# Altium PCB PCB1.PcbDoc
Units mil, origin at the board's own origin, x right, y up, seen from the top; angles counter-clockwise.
Board outline 3900 x 2015 mil, 2 copper layers (Top Layer, Bottom Layer); 36 components, 29 nets, 156 pads, 48 vias.
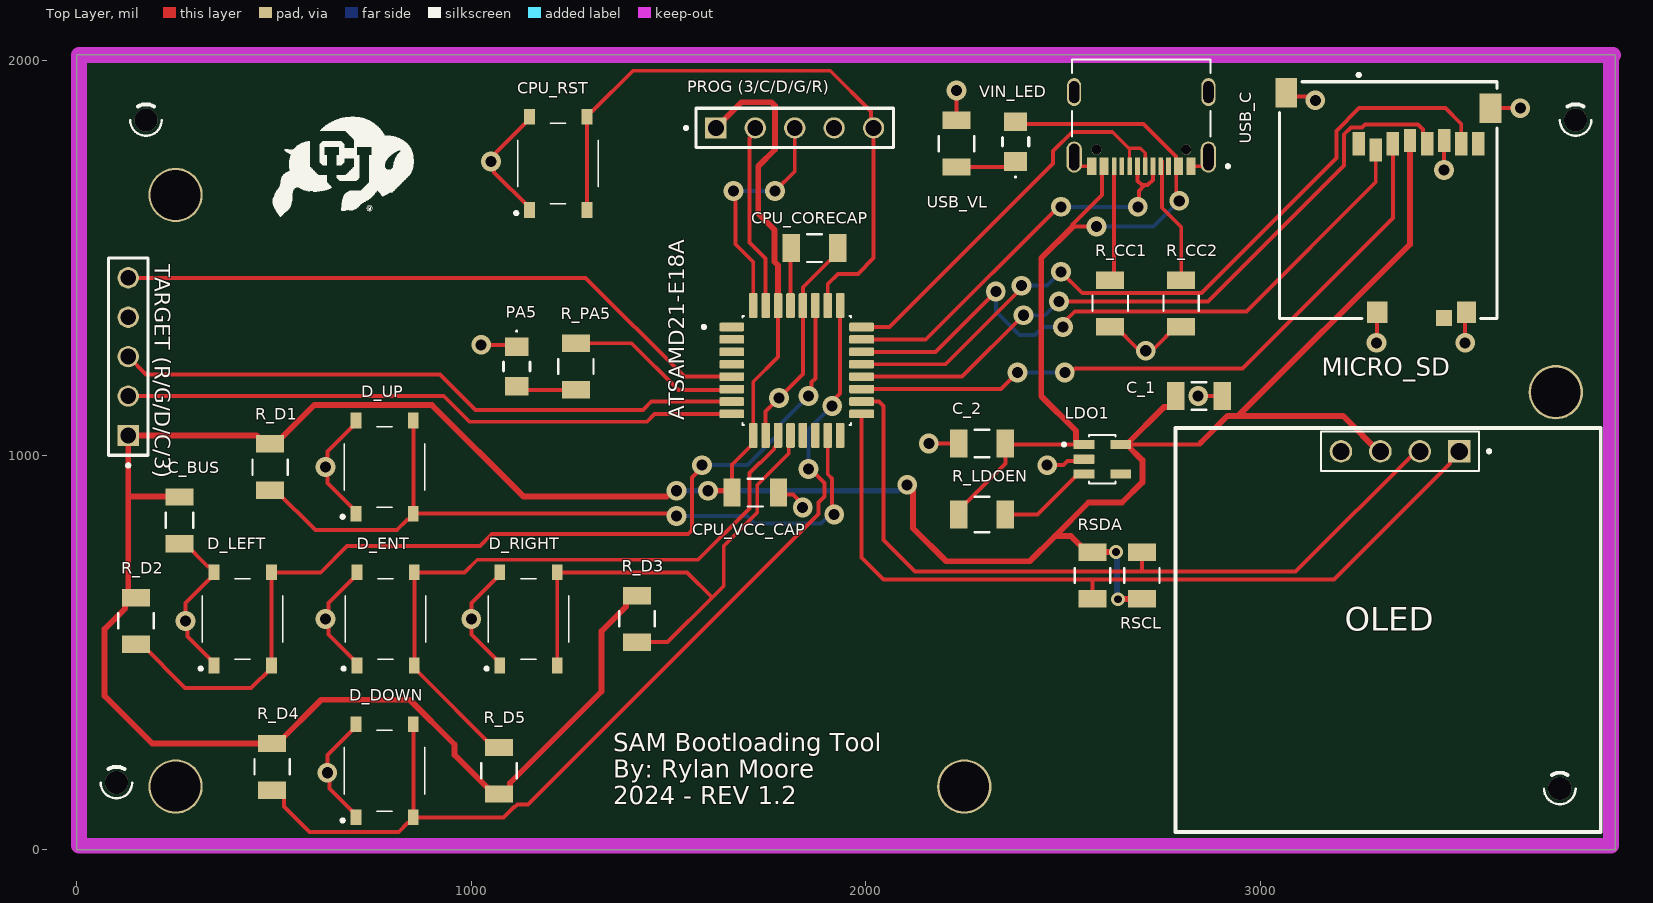
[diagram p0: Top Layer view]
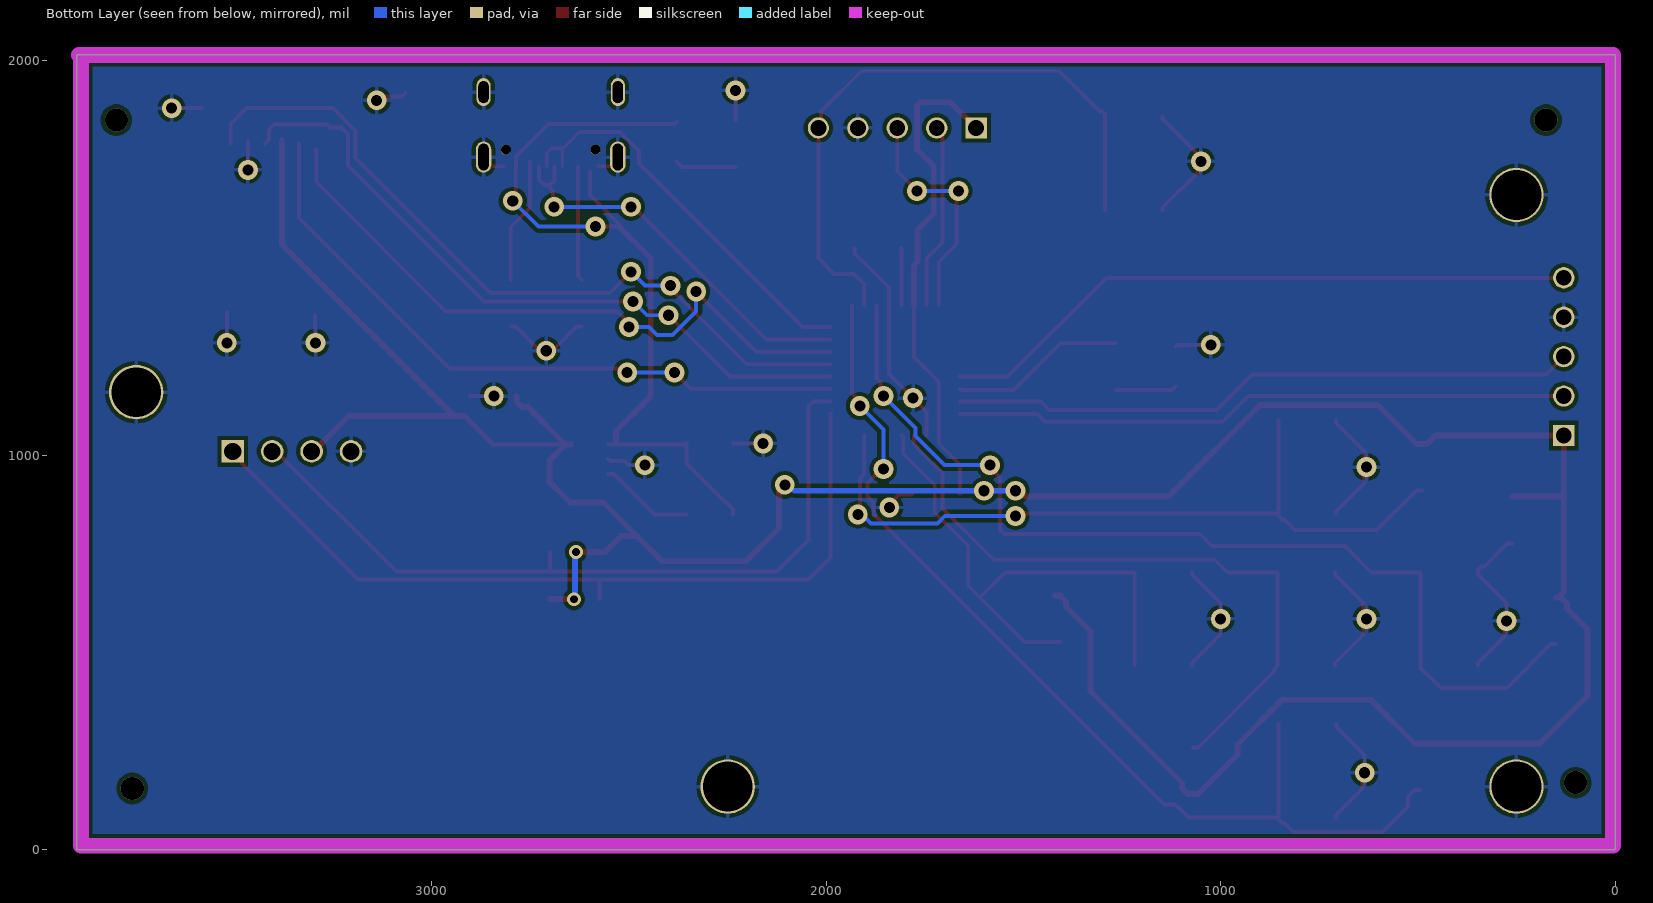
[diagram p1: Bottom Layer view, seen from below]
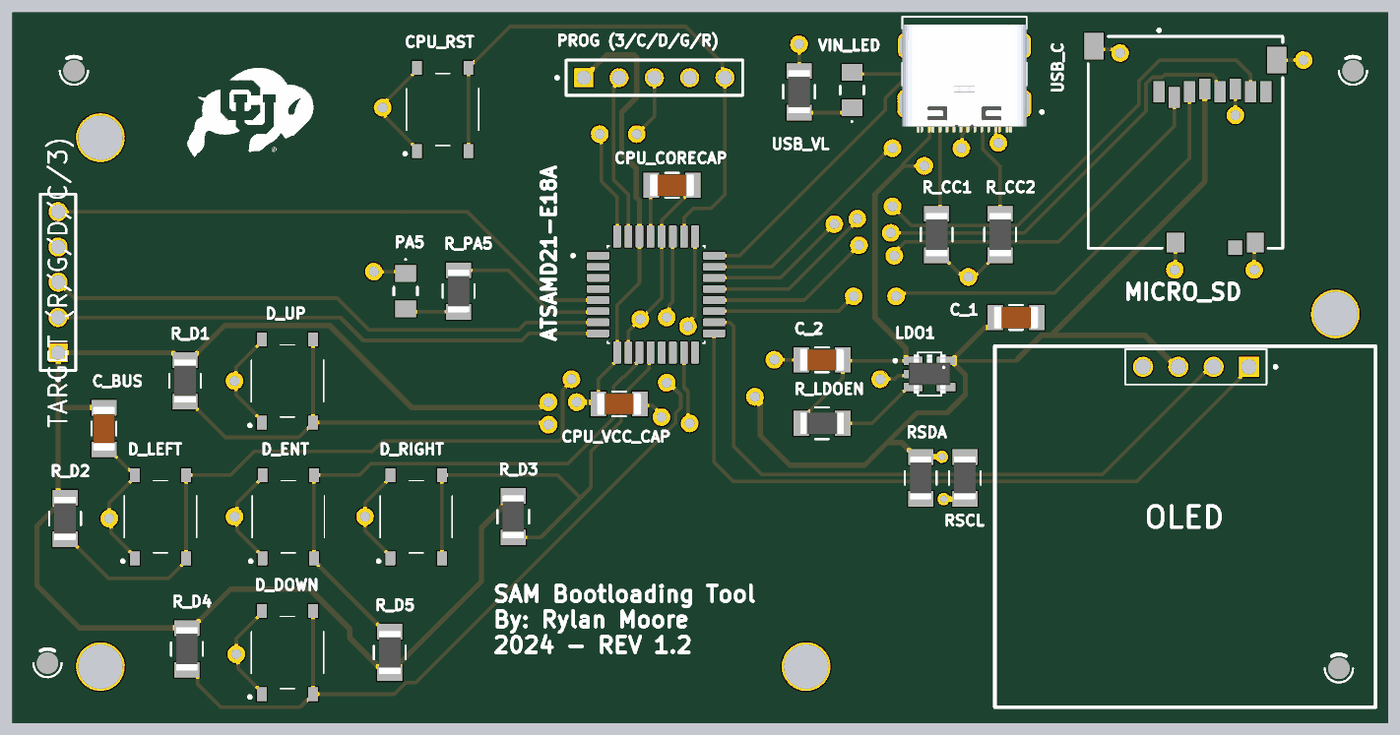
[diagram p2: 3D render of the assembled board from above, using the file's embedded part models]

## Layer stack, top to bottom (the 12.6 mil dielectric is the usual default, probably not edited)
Top Solder: solder mask 0.4, Solder Resist, Dk 3.5
Top Layer: signal copper 1.4
Dielectric 1: dielectric 12.6, FR-4, Dk 4.8
Bottom Layer: signal copper 1.4
Bottom Solder: solder mask 0.4, Solder Resist, Dk 3.5

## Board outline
0,0 3900,0 3900,2015 0,2015

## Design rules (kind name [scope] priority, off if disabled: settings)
Clearance [All] p1: gap=10 ignorepadtopadclearanceinfootprint=FALSE except(0: Arc-Hole Track-Hole SMDPad-Hole THPad-Hole Via-Hole Fill-Hole Poly-Hole Region-Hole Text-Hole; 6: Arc-SMDPad Track-SMDPad SMDPad-SMDPad SMDPad-THPad)
PolygonConnect [All] p1: connectstyle=Relief reliefconductorwidth=10 reliefentries=4 polygonreliefangle="90 Angle" airgapwidth=10
RoutingVias [All] p1: holewidth=28 width=50 viastyle="Through Hole" minholewidth=28 minwidth=50 maxholewidth=28 maxwidth=50
SolderMaskExpansion [All] p1: expansion=4 istentingtop=FALSE
Width Width_1 [InNet('USB_POWER')] p1: maxlimit=20 minlimit=10 preferedwidth=15
Width Width_2 [InNet('3.3V')] p2: maxlimit=20 minlimit=10 preferedwidth=15
Width [All] p3: maxlimit=10 minlimit=7 preferedwidth=10
30 further rules are at their usual default settings.

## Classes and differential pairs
component class microcontroller: ATSAMD21-E18A C_1 C_2 CPU_CORECAP CPU_R CPU_RST CPU_VCC_CAP CPUCORE_CAP GND_1 H1 H2 H3 H4 LDO1 PA5 "Pg (R/G/D/C/3)" "PROG (3/C/D/G/R)" R_CC1 R_CC2 R_LDOEN R_PA5 USB_C USB_VL VIN_LED
component class d_pad: C_BUS D_DOWN D_ENT D_LEFT D_RIGHT D_UP OLED "Pg (R/G/D/C/3)2" R_D1 R_D2 R_D3 R_D4 R_D5 RSCL RSDA "TARGET (R/G/D/C/3)"

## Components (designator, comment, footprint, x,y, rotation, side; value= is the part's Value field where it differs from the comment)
ATSAMD21-E18A "ATSAMD21E18A-AUT" QFP80P900X900X120-32N 1825,1215 r0 top
C_1 "22uF" 1206_Passive_Capacitor 2845,1150 r180 top
C_2 "22uF" 1206_Passive_Capacitor 2295,1030 r0 top
C_BUS "10uF" 1206_Passive_Capacitor 260,835 r90 top value=22uF
CPU_CORECAP "22uF" 1206_Passive_Capacitor 1870,1525 r0 top value=1uF
CPU_RST "PTS526_SM15_SMTR2_LFS" PTS526SM15SMTR2LFS 1220,1740 r90 top
CPU_VCC_CAP "22uF" 1206_Passive_Capacitor 1720,905 r180 top
D_DOWN "PTS526_SM15_SMTR2_LFS" PTS526SM15SMTR2LFS 780,200 r90 top
D_ENT "PTS526_SM15_SMTR2_LFS" PTS526SM15SMTR2LFS 782.5,585 r90 top
D_LEFT "PTS526_SM15_SMTR2_LFS" PTS526SM15SMTR2LFS 420,585 r90 top
D_RIGHT "PTS526_SM15_SMTR2_LFS" PTS526SM15SMTR2LFS 1145,585 r90 top
D_UP "PTS526_SM15_SMTR2_LFS" PTS526SM15SMTR2LFS 780,970 r90 top
H1 "Stencil Hole" AlignmentHole_1.5mm 3760,155 r0 top
H2 "Stencil Hole" AlignmentHole_1.5mm 3800,1850 r0 top
H3 "Stencil Hole" AlignmentHole_1.5mm 100,170 r0 top
H4 "Stencil Hole" AlignmentHole_1.5mm 175,1850 r0 top
LDO1 "AP2112K-3.3TRG1" SOT95P285X140-5N 2600,990 r0 top
MICRO_SD "MEM2052-00-195-00-A_REVA" GCT_MEM2052-00-195-00-A_REVA 3325.16,1646.89 r180 top
OLED "61300411121" WURTH_61300411121 3355,1010 r180 top
PA5 "CD1206-S01575" BOUR-CD1206-S01575-2_L 1115,1225 r90 top
"PROG (3/C/D/G/R)" "MTSW-105-12-S-S-480" SAMTEC_MTSW-105-12-S-S-480 1820,1830 r180 top (schematic designator "PROG (R/G/D/C/3)")
R_CC1 "100KOhm" 1206_Passive_Resitor 2620,1385 r270 top value=5.1kOhm
R_CC2 "100KOhm" 1206_Passive_Resitor 2800,1385 r90 top value=5.1KOhm
R_D1 "100Ohm" 1206_Passive_Resitor 490,970 r90 top value=10kOhm
R_D2 "100Ohm" 1206_Passive_Resitor 150,580 r90 top value=10kOhm
R_D3 "100Ohm" 1206_Passive_Resitor 1420,585 r90 top value=10kOhm
R_D4 "100Ohm" 1206_Passive_Resitor 495,210 r90 top value=10kOhm
R_D5 "100Ohm" 1206_Passive_Resitor 1070,200 r270 top value=10kOhm
R_LDOEN "1 Ohm" 1206_Passive_Resitor 2295,850 r0 top value=10kOhm
R_PA5 "100Ohm" 1206_Passive_Resitor 1265,1225 r90 top value="300 Ohm"
RSCL "100Ohm" 1206_Passive_Resitor 2700,695 r270 top value=10kOhm
RSDA "100Ohm" 1206_Passive_Resitor 2575,695 r90 top value=10kOhm
"TARGET (R/G/D/C/3)" "MTSW-105-12-S-S-480" SAMTEC_MTSW-105-12-S-S-480 130,1250 r270 top
USB_C "CSP-USC16-TR" VALCON_CSP-USC16-TR 2698.78,1732.87 r180 top
USB_VL "100Ohm" 1206_Passive_Resitor 2230,1790 r90 top value=1kOhm
VIN_LED "CD1206-S01575" BOUR-CD1206-S01575-2_L 2380,1795 r270 top

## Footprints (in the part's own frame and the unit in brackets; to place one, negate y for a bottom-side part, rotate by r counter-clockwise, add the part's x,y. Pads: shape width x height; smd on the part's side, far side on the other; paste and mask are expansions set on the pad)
1206_Passive_Capacitor [mil]
  rect 44x71 smd: 1(-59,0) 2(59,0)
  silkscreen extent -19,-35 19,35, body extent -63,-31 63,32, height 50
1206_Passive_Resitor [mil]
  rect 44x71 smd: 1(-59,0) 2(59,0)
  silkscreen extent -19,-45 19,45, body extent -61,-31 61,31, height 26
AlignmentHole_1.5mm [mm]
  round 1.55 on Top Paste paste+0 mask+0: 1(0,0)
  silkscreen extent -1.02,-1.01 1.02,1.01
BOUR-CD1206-S01575-2_L [mm] "Molded Diode, 2-Leads, Body 3.4x1.7mm, IPC High Density"
  rect 1.2x1.5 smd: 1(-1.275,0) 2(1.275,0)
  silkscreen extent -0.28,-0.85 2.32,0.85, body extent -1.7,-0.85 1.7,0.85, height 0.95
GCT_MEM2052-00-195-00-A_REVA [mm]
  rect 1.4x1.9 smd: G1(-6.575,-5.925) G2(6.575,-6.925)
  rect 1.2x1.4 smd: G3(-5.035,7.225)
  rect 1.3x1.4 smd: G4(0.715,7.225)
  rect 0.8x1.5 smd: P1(1.905,-3.635) P2(0.805,-3.235) P3(-0.295,-3.635) P4(-1.395,-3.835) P5(-2.495,-3.635) P6(-3.595,-3.835) P7(-4.695,-3.635) P8(-5.795,-3.635)
  rect 1x1.04 smd: P9(-3.585,7.595)
  silkscreen extent -7,-8.16 7,7.63
PTS526SM15SMTR2LFS [mm]
  rect 1x0.7 smd: 1(-3,1.85) 2(3,1.85) 3(-3,-1.85) 4(3,-1.85)
  silkscreen extent -3.3,-2.6 2.6,2.8
QFP80P900X900X120-32N [mm]
  rrect25% 1.6x0.55 smd: 1(-4.18,2.8) 2(-4.18,2) 3(-4.18,1.2) 4(-4.18,0.4) 5(-4.18,-0.4) 6(-4.18,-1.2) 7(-4.18,-2) 8(-4.18,-2.8) 17(4.18,-2.8) 18(4.18,-2) 19(4.18,-1.2) 20(4.18,-0.4) 21(4.18,0.4) 22(4.18,1.2) 23(4.18,2) 24(4.18,2.8)
  rrect25% 0.55x1.6 smd: 9(-2.8,-4.18) 10(-2,-4.18) 11(-1.2,-4.18) 12(-0.4,-4.18) 13(0.4,-4.18) 14(1.2,-4.18) 15(2,-4.18) 16(2.8,-4.18) 25(2.8,4.18) 26(2,4.18) 27(1.2,4.18) 28(0.4,4.18) 29(-0.4,4.18) 30(-1.2,4.18) 31(-2,4.18) 32(-2.8,4.18)
  silkscreen extent -6.08,-3.5 3.5,3.5
SAMTEC_MTSW-105-12-S-S-480 [mm]
  rect 1.37x1.37 hole 1.02: 01(5.08,0)
  round 1.37 hole 1.02: 02(2.54,0) 03(0,0) 04(-2.54,0) 05(-5.08,0)
  silkscreen extent -6.35,-1.27 7.1,1.27
SOT95P285X140-5N [mm]
  rrect15% 1.35x0.6 smd: 1(-1.185,0.95) 2(-1.185,0) 3(-1.185,-0.95) 4(1.185,-0.95) 5(1.185,0.95)
  silkscreen extent -2.57,-1.55 0.85,1.55, body extent -1.5,-1.4 1.5,1.4, height 1.4
VALCON_CSP-USC16-TR [mm]
  rect 0.3x1.14 smd: A1(-3.35,0) A4(-2.55,0) A5(-1.25,0) A6(-0.25,0) A7(0.25,0) A8(1.25,0) A9(2.55,0) A12(3.35,0) B1(3.05,0) B4(2.25,0) B5(1.75,0) B6(0.75,0) B7(-0.75,0) B8(-1.75,0) B9(-2.25,0) B12(-3.05,0)
  oval 1x2 hole 0.65 slot 1.72 at 90 deg: S1(-4.325,-0.59) S2(4.325,-0.59)
  oval 0.9x1.8 hole 0.65 slot 1.4 at 90 deg: S3(-4.325,-4.77) S4(4.325,-4.77)
  round 0.65 hole 0.65 unplated: ""(-2.89,-1.07) ""(2.89,-1.07)
  silkscreen extent -5.68,-6.86 4.47,0.1, body extent -4.47,-6.28 4.47,1.47, height 3.26
WURTH_61300411121 [mm]
  rect 1.45x1.45 hole 1.1: 01(-3.81,0)
  round 1.45 hole 1.1: 02(-1.27,0) 03(1.27,0) 04(3.81,0)
  silkscreen extent -5.83,-1.27 5.08,1.27

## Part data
ATSAMD21-E18A: "ARM Cortex-M0+ SAM D21E Microcontroller IC 32-Bit 48MHz 256KB (256K x 8) FLASH 32-TQFP (7x7)", Package=None
C_1 C_2 CPU_CORECAP CPU_VCC_CAP: library part C_22uF_1206, "22uF ±10% 25V X5R 1206 Multilayer Ceramic Capacitors MLCC - SMD/SMT RoHS", LCSC Part#=C12891, MFR Part #=CL31A226KAHNNNE
C_BUS: library part C_10uF_1206, "10uF ±10% 50V X5R 1206 Multilayer Ceramic Capacitors MLCC - SMD/SMT RoHS", LCSC Part#=C13585, MFR Part #=CL31A106KBHNNNE
CPU_RST D_DOWN D_ENT D_LEFT D_RIGHT D_UP: library part CMP-005-000000-1, "Tactile Switch SPST-NO Top Actuated Surface Mount", Package=None
H1 H2 H3 H4: library part H_StencilAllignment_1.5mm, "Stencil Allignment hole for use with 1.5mm pin"
LDO1: "AP2112 Series 0.6 A 3.3 V Fixed Output SMT LDO Linear Regulator - SOT23-5", Package=None
MICRO_SD "PROG (3/C/D/G/R)" "TARGET (R/G/D/C/3)" USB_C: Package=None
OLED: "<a href=\"https://pricing.snapeda.com/parts/61300411121/W%C3%BCrth%20Elektronik/view-part?ref=eda\">Check availability</a>", Package=None
PA5 VIN_LED: library part CMP-0583-00001-2, "75 V Small Signal Switching Diode, 150 mA, 2.5 uA, 1026 Molded Package, RoHS, Tape and Reel", Average Forward Current="150 mA", Capacitance Between Terminals (Max.)="3 pF", Forward Voltage (Max.)="1.00 V", Manufacturer=Bourns, Reverse Current (Max.)="2.5 uA", Reverse Voltage="75 V"
R_CC1 R_CC2: library part R_100KOhm_1206, "100kΩ ±1% 0.25W ±100ppm/℃ 1206 Chip Resistor - Surface Mount RoHS", LCSC Part#=C17900, MFR Part #=1206W4F1003T5E
R_D1 R_D2 R_D3 R_D4 R_D5 R_PA5 RSCL RSDA USB_VL: library part R_100Ohm_1206, "100Ω ±1% 0.25W ±100ppm/℃ 1206 Chip Resistor - Surface Mount RoHS", LCSC Part#=C17901, MFR Part #=1206W4F1000T5E
R_LDOEN: library part R_1Ohm_1206, "1Ω ±5% 0.25W ±400ppm/℃ 1206 Chip Resistor - Surface Mount RoHS", LCSC Part#=C1409, MFR Part #=1206W4J010JT5E

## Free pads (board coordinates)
  round 137.79 hole 125.98: 4(250,160) 4(250,1660) 4(2250,160) 4(3750,1160)

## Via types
v1: diameter 50, hole 28, Top Layer to Bottom Layer, 42 vias
v2: diameter 59.06, hole 59.06, Top Layer to Bottom Layer, 4 vias
v3: diameter 35, hole 20, Top Layer to Bottom Layer, 2 vias

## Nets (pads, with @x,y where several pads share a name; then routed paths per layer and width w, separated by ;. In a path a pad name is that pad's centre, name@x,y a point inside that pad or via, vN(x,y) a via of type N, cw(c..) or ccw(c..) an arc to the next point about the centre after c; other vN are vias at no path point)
3.3V: "PROG (3/C/D/G/R).01" "TARGET (R/G/D/C/3).01" ATSAMD21-E18A.9 ATSAMD21-E18A.30 C_1.2 C_BUS.2 CPU_VCC_CAP.2 LDO1.5 MICRO_SD.P4 OLED.03 R_D1.2 R_D2.2 R_D3.2 R_D4.2 R_D5.2 RSCL.2 RSDA.2 | length 9163.5
  Top Layer w10: CPU_VCC_CAP.2 1661,976 1714.76,1029.76 ATSAMD21-E18A.9 1714.76,1186.42 1777.76,1249.41 ATSAMD21-E18A.30 ; LDO1.5@2661.42,1027.4 2847.6,1027.4
  Top Layer w15: R_D2.2 R_D2.2@144.5,639 ; C_BUS.2 259,895 130,895 ; R_D3.2 1406.5,644 1392,629.5 1392,616 1330,554 1330,401 1098,169 1098,155.5 1083.5,141 R_D5.2 1056.5,141 957.1,240.4 957.1,266.4 843.5,380 619.5,380 508.5,269 R_D4.2 191,269 70,390 70,559 122,611 122,624.5 136.5,639 R_D2.2@144.5,639 ; 1495.53,895 1132.5,895 900,1127.5 602,1127.5 503.5,1029 R_D1.2 476.5,1029 455.5,1050 130,1050 130,895 ; v1(1600,910) 1656,910 CPU_VCC_CAP.2 ; 1620,1830 1685,1895 1761.21,1895 1770,1886.21 1770,1775.33 1727.5,1732.83 1727.5,1613.16 1768.76,1571.9 1768.76,1490.65 1777.76,1481.65 ATSAMD21-E18A.30 ; v1(2105,925) 2120,910 2120,815 2203.79,731.21 2416.21,731.21 2480,795 ; v3(2635,755) 2634.5,754.5 2575.5,754.5 RSDA.2 2561.5,754 2520.5,795 2480,795 ; v3(2640,635) 2640.5,635.5 2699.5,635.5 RSCL.2 ; LDO1.5 LDO1.5@2661.42,1027.4 ; C_1.2 2786,1136.5 2771.5,1122 2756.02,1122 LDO1.5@2661.42,1027.4 ; 2850,1032.5 2917.5,1100 2945,1100 ; OLED.03@3305.86,1004.14 3210,1100 2945,1100 ; MICRO_SD.P4 3379.92,1797.72 3379.92,1534.92 2945,1100 ; 130,895 130,653.5 R_D2.2@144.5,639 ; 2480,795 2565,880 2650,880 2701.29,931.29 2701.29,987.53 LDO1.5@2661.42,1027.4
  Bottom Layer w15: v1(1520,910) v1(1600,910) 2080.53,910 ; v3(2635,755) 2637.5,752.5 2637.5,637.5 v3(2640,635)
CLK: "PROG (3/C/D/G/R).02" ATSAMD21-E18A.31 | length 473.7
  Top Layer w10: 1720,1830 1720,1818.11 1705,1803.11 1705,1540 1746.26,1498.74 ATSAMD21-E18A.31
CS: ATSAMD21-E18A.22 MICRO_SD.P2 | length 1689.6
  Top Layer w10: ATSAMD21-E18A.22 2177.24,1262.24 v1(2330,1415) ; v1(2500,1325) 2500,1335 2530,1365 2965,1365 3293.31,1693.31 3293.31,1774.09 MICRO_SD.P2
  Bottom Layer w10: v1(2330,1415) 2330,1365 2390,1305 2429.59,1305 2449.59,1325 v1(2500,1325)
D+: ATSAMD21-E18A.24 USB_C.A6 USB_C.B6 | length 1044.9
  Top Layer w8: 2625,1820 2666.47,1778.53 ; USB_C.B6 2669.25,1775.75 2666.47,1778.53 ; USB_C.A6 2708.62,1766.38 2696.47,1778.53 2666.47,1778.53
  Top Layer w10: ATSAMD21-E18A.24 2060.24,1325.24 2475,1740 2475,1771.34 2523.66,1820 2625,1820
D-: ATSAMD21-E18A.23 USB_C.A7 USB_C.B7 | length 1022.8
  Top Layer w10: ATSAMD21-E18A.23 2152.17,1293.74 2488.43,1630 v1(2495,1630) ; USB_C.A7 2689.57,1732.24 2689.57,1695.43 2700,1685 2707.5,1685 ; v1(2690,1630) 2692.5,1632.5 2692.5,1670 2707.5,1685 ; USB_C.B7 2728.31,1698.31 2715,1685 2707.5,1685
  Bottom Layer w10: v1(2495,1630) v1(2690,1630)
D_DOWN: ATSAMD21-E18A.25 D_DOWN.3 D_DOWN.4 R_D4.1 | length 2582
  Top Layer w10: R_D4.1 508.5,151 525.5,134 525.5,109.5 590,45 815.94,45 838.15,67.2 844.05,67.2 852.83,75.98 D_DOWN.3 ; D_DOWN.4 D_DOWN.3 ; v1@1872.24,952.76 1895,930 1895,895 1880,880 1880,850.93 1143.51,114.44 1116.5,114.44 1110.06,108 1108,108 1081.89,81.89 D_DOWN.3 ; v1(1915,1125) 1915,1135.82 1935.24,1156.06 ATSAMD21-E18A.25
  Bottom Layer w10: v1(1855,965) 1855,1065 v1(1915,1125)
D_ENT: ATSAMD21-E18A.11 D_ENT.3 D_ENT.4 R_D5.1 | length 1674.5
  Top Layer w10: R_D5.1 1056.5,259 864.11,451.39 864.11,458.11 D_ENT.3 D_ENT.4 983.11,703.11 1015,735 1575,735 1705,865 1705,955 1730.47,980.47 1732.59,980.47 1768.09,1015.97 1768.09,1020.09 1777.76,1029.76 ATSAMD21-E18A.11
D_LEFT: ATSAMD21-E18A.27 D_LEFT.3 D_LEFT.4 R_D2.1 | length 2529.8
  Top Layer w10: R_D2.1 163.5,521 274.5,410 441.85,410 492.83,460.98 D_LEFT.3 D_LEFT.4 618.11,703.11 685,770 1021.72,770 1051.72,800 1550,800 1560,810 1560,944.14 1585,969.14 v1(1585,975) ; v1(1855,1150) 1862.65,1157.65 1862.65,1185.41 1872.24,1195 ATSAMD21-E18A.27
  Bottom Layer w10: v1(1585,975) 1700,975 1773.67,1048.67 1773.67,1068.67 v1(1855,1150)
D_RIGHT: ATSAMD21-E18A.12 D_RIGHT.3 D_RIGHT.4 R_D3.1 | length 1400.4
  Top Layer w10: D_RIGHT.3 D_RIGHT.4 1546.89,703.11 1610.86,639.14 ; R_D3.1@1406.5,526 1497.72,526 1610.86,639.14 ; ATSAMD21-E18A.12 1804.88,1046.06 1804.88,1003.94 1725,924.06 1725,855 1640,770 1640,668.28 1610.86,639.14
D_UP: ATSAMD21-E18A.15 D_UP.3 D_UP.4 R_D1.1 | length 1955.6
  Top Layer w10: R_D1.1 503.5,911 604.5,810 810.94,810 838.15,837.2 844.05,837.2 852.83,845.98 D_UP.3 ; D_UP.4 D_UP.3 ; v1(1520,845.94) 1514.06,851.89 D_UP.3 ; ATSAMD21-E18A.15 1903.74,951.84 1915,940.58 1915,854.67 v1(1919.98,849.69)
  Bottom Layer w10: v1(1520,845.94) 1699.67,845.94 1718.12,827.5 1886.97,827.5 1909.16,849.69 v1(1919.98,849.69)
DIO: "PROG (3/C/D/G/R).03" ATSAMD21-E18A.32 | length 596.8
  Top Layer w10: v1(1665,1670) 1670,1665 1670,1535 1714.76,1490.24 ATSAMD21-E18A.32 ; v1(1770,1670) 1820,1720 1820,1830
  Bottom Layer w10: v1(1665,1670) v1(1770,1670)
DUT_RST: "TARGET (R/G/D/C/3).05" ATSAMD21-E18A.5 | length 1634.3
  Top Layer w10: 130,1450 1290,1450 1540.75,1199.25 ATSAMD21-E18A.5
DUT_SWCLK: "TARGET (R/G/D/C/3).02" ATSAMD21-E18A.8 | length 1565.5
  Top Layer w10: 130,1150 930,1150 995,1085 1445,1085 1464.76,1104.76 ATSAMD21-E18A.8
DUT_SWDIO: "TARGET (R/G/D/C/3).03" ATSAMD21-E18A.7 | length 1595.2
  Top Layer w10: 130,1250 175,1205 920,1205 1010,1115 1435,1115 1456.26,1136.26 ATSAMD21-E18A.7
GND: "PROG (3/C/D/G/R).04" "TARGET (R/G/D/C/3).04" ATSAMD21-E18A.10 ATSAMD21-E18A.28 C_1.1 C_2.1 C_BUS.1 CPU_CORECAP.2 CPU_RST.1 CPU_RST.2 CPU_VCC_CAP.1 D_DOWN.1 D_DOWN.2 D_ENT.1 D_ENT.2 D_LEFT.1 D_LEFT.2 D_RIGHT.1 D_RIGHT.2 D_UP.1 D_UP.2 LDO1.2 MICRO_SD.G1 MICRO_SD.G2 MICRO_SD.G3 MICRO_SD.G4 MICRO_SD.P6 OLED.04 PA5.2 pad.4 R_CC1.2 R_CC2.1 USB_C.A1 USB_C.A12 USB_C.B1 USB_C.B12 USB_C.S1 USB_C.S2 USB_C.S3 USB_C.S4 USB_VL.2 | length 3710.4
  Top Layer w10: C_BUS.1 273.5,776 331.7,717.8 338.39,717.8 347.17,709.02 D_LEFT.2 347.17,697.2 275,625.04 v1(275,580) 279.96,575.04 279.96,540 347.17,472.8 D_LEFT.1 ; D_DOWN.1 707.17,87.8 639.96,155 639.96,190.04 v1(635,195) 635,240.04 707.17,312.2 D_DOWN.2 ; D_UP.1 707.17,857.8 634.96,930 634.96,965.04 v1(630,970) 634.96,974.96 634.96,1010 707.17,1082.2 D_UP.2 ; D_ENT.1 709.67,472.8 637.46,545 637.46,577.54 v1(630,585) 637.46,592.46 637.46,625 709.67,697.2 D_ENT.2 ; v1(1025,1280) 1110.2,1280 PA5.2 ; D_RIGHT.1 1072.17,472.8 1000,544.96 v1(1000,585) 1000,625.04 1072.17,697.2 D_RIGHT.2 ; CPU_RST.1 1147.17,1627.8 1057.65,1717.31 1057.65,1737.35 v1(1050,1745) 1050,1755.04 1147.17,1852.2 CPU_RST.2 ; ATSAMD21-E18A.10 1746.26,1111.26 v1(1780,1145) 1840.75,1205.75 ATSAMD21-E18A.28 1840.75,1426.06 1909.18,1494.5 1912,1494.5 1929,1511.5 CPU_CORECAP.2 ; CPU_VCC_CAP.1 1784,900 1816,900 1840,876 v1(1840,867.5) ; v1(2160,1030) C_2.1 ; USB_VL.2 v1(2230,1925) ; v1(2460,975) 2501.03,975 2511.77,985.74 2549.09,985.74 LDO1.2 ; USB_C.S2 2528.5,1746.44 2542.07,1732.87 USB_C.A12 USB_C.B1 ; R_CC1.2 2633.5,1326 2686.85,1272.65 2702.35,1272.65 v1(2710,1265) 2717.65,1272.65 2733.15,1272.65 2786.5,1326 R_CC2.1 ; USB_C.B12 USB_C.A1 2855.49,1732.87 2869.06,1746.44 USB_C.S1 ; v1(2843,1150) C_1.1 ; MICRO_SD.G2 3075.83,1910 3119.18,1910 3129.18,1900 v1(3140,1900) ; v1(3295,1285) 3296.85,1283.15 MICRO_SD.G4@3296.85,1355 ; v1@3465,1725 v1(3466.54,1723.46) MICRO_SD.P6@3466.54,1795 ; v1(3520,1285) MICRO_SD.G3@3520,1362.44 ; MICRO_SD.G1@3584.33,1880 v1(3660,1880)
MISO: ATSAMD21-E18A.21 MICRO_SD.P7 | length 1944.9
  Top Layer w10: ATSAMD21-E18A.21 2202.32,1230.75 2395,1423.43 v1(2395,1430) ; v1(2495,1465) 2549,1411 2851,1411 3193.28,1753.28 3193.28,1822.24 3251.04,1880 3470,1880 3510,1840 MICRO_SD.P7
  Bottom Layer w10: v1(2395,1430) 2460,1430 v1(2495,1465)
MOSI: ATSAMD21-E18A.19 MICRO_SD.P3 | length 1715.2
  Top Layer w10: ATSAMD21-E18A.19 2342.76,1167.76 v1(2385,1210) ; v1(2505,1210) 2512.65,1217.65 2528.51,1217.65 2530.86,1220 2955,1220 3336.61,1601.61 3336.61,1789.84 MICRO_SD.P3
  Bottom Layer w10: v1(2385,1210) v1(2505,1210)
NetATSAMD21-E18A_6: ATSAMD21-E18A.6 R_PA5.2 | length 445.9
  Top Layer w10: R_PA5.2 1406,1284 1525,1165 1657.68,1165 ATSAMD21-E18A.6
NetATSAMD21-E18A_26: "PROG (3/C/D/G/R).05" ATSAMD21-E18A.26 CPU_RST.3 CPU_RST.4 | length 1623.7
  Top Layer w10: CPU_RST.3 CPU_RST.4 1292.83,1864.02 1301.61,1872.8 1307.52,1872.8 1409.72,1975 1910,1975 2013.03,1871.97 2013.03,1836.97 2020,1830 2020,1500 1980,1460 1930,1460 1903.74,1433.74 ATSAMD21-E18A.26
NetATSAMD21-E18A_29: ATSAMD21-E18A.29 CPU_CORECAP.1 | length 146.2
  Top Layer w10: ATSAMD21-E18A.29 1809.25,1523.25 CPU_CORECAP.1
NetLDO1_3: LDO1.3 R_LDOEN.2 | length 241.8
  Top Layer w10: R_LDOEN.2 2435.98,850 2538.58,952.6 LDO1.3
NetPA5_1: PA5.1 R_PA5.1 | length 153.6
  Top Layer w10: PA5.1 1123.8,1166 R_PA5.1
NetR_CC1_1: R_CC1.1 USB_C.B5 | length 293
  Top Layer w10: R_CC1.1 2629.88,1453.88 USB_C.B5
NetR_CC2_2: R_CC2.2 USB_C.A5 | length 321.4
  Top Layer w10: USB_C.A5@2750.77,1745 2750.77,1627.61 2800,1578.39 R_CC2.2
NetUSB_VL_1: USB_VL.1 VIN_LED.2 | length 155.7
  Top Layer w10: USB_VL.1 2366.2,1731 VIN_LED.2
SCK: ATSAMD21-E18A.20 MICRO_SD.P5 | length 1779.7
  Top Layer w10: ATSAMD21-E18A.20 2244.25,1199.25 v1(2400,1355) ; v1(2490,1390) 2868.28,1390 3213.28,1735 3213.28,1813.96 3230.57,1831.24 3258.85,1831.24 3266.01,1838.4 3400.38,1838.4 3412.64,1826.15 3412.64,1800.75 MICRO_SD.P5
  Bottom Layer w10: v1(2400,1355) 2455,1355 v1(2490,1390)
SCL: ATSAMD21-E18A.18 OLED.02 RSCL.1 | length 1972.8
  Top Layer w10: ATSAMD21-E18A.18 2033.74,1136.26 2045,1125 2045,785 2125,705 2700,705 ; RSCL.1 2700,705 ; OLED.02@3405,1020.13 3089.87,705 2700,705
SDA: ATSAMD21-E18A.17 OLED.01 RSDA.1 | length 2101.7
  Top Layer w10: ATSAMD21-E18A.17 1989.57,740.43 2045,685 2575,685 ; RSDA.1 2575,685 ; OLED.01@3515,1012.98 3507.98,1012.98 3481.46,986.46 3481.46,979.43 3187.02,685 2575,685
USB_POWER: C_2.2 LDO1.1 R_LDOEN.1 USB_C.A4 USB_C.A9 USB_C.B4 USB_C.B9 VIN_LED.1 | length 2062.5
  Top Layer w10: R_LDOEN.1 2236,863.5 2253,880.5 2255,880.5 2354,979.5 C_2.2 2356.6,1027.4 LDO1.1@2540.35,1027.4 ; VIN_LED.1 2385.2,1840 2704.45,1840 2786.46,1758 2786.46,1733.78 USB_C.B9 v1@2787.36,1657.36 ; 2524.8,1579.8 2524.8,1584.8 2599.61,1659.61 USB_C.A9@2599.61,1720 ; 2529.61,1580 v1(2585,1580) ; LDO1.1@2533.54,1034.21 LDO1.1@2540.35,1027.4 ; LDO1.1 LDO1.1@2540.35,1027.4
  Top Layer w15: 2524.8,1579.8 2445,1500 2445,1150 2533.54,1061.46 LDO1.1@2533.54,1034.21
  Bottom Layer w10: v1(2585,1580) 2730,1580 v1(2795,1645)
pads on no net: ATSAMD21-E18A.1 ATSAMD21-E18A.2 ATSAMD21-E18A.3 ATSAMD21-E18A.4 ATSAMD21-E18A.13 ATSAMD21-E18A.14 ATSAMD21-E18A.16 H1.1 H2.1 H3.1 H4.1 LDO1.4 MICRO_SD.P1 MICRO_SD.P8 MICRO_SD.P9 USB_C. USB_C.A8 USB_C.B8
copper on no net:
  other v2: 3760,155 100,170 175,1850 3800,1850

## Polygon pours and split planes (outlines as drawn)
GND on Bottom Layer "GND_L02_P002" (solid, pour order 2): 0,0 3900,0 3900,2015 0,2015

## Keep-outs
Keep-Out Layer:
  lines w40: 3890,2010 3890,10 5,10 5,2015 3895,2015

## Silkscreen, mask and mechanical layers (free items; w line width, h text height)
Top Overlay:
  drawing of 8 lines, arcs and shapes, not listed
  text "SAM Bootloading Tool / By: Rylan Moore / 2024 - REV 1.2" at 1360,115 h45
